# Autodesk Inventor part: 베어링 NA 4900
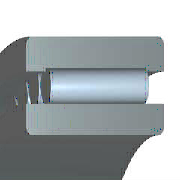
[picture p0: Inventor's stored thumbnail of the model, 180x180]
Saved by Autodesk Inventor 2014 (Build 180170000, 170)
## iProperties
Created: 2009-02
Part Number: 베어링 NA 4900
Material: 스테인리스강
Description: 니들 롤러 베어링 - 경계 치수 및 공차
Document SubType Name: Modeling
Standard: KS B 2029
Designer: SeoGD™
Standards Organization: KS
Language: ko-KR
Size Designation: NA 4900 - 10 x 22 x 13
Categories: <MemberInstance><Categories><Category DisplayName="샤프트 부품" InternalName="7f7aeb1f-a693-4053-b835-cee3144e0d98" Mnemonic="SHFT"><Category DisplayName="베어링" Inter
Density: 8.08 g/cm^3
Appearance: 반광택
Mass: 24.488 g
Surface Area: 38.613 cm^2
Volume: 3.0307 cm^3
IsCustomPart: 0
Author: SeoGD™
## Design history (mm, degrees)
sketch "스케치"
  geometry: L1 (1.857, 9)-(11.143, 9); L2 (11.143, 9)-(11.143, 7); L3 (13, 7)-(0, 7); L4 (1.857, 7)-(1.857, 9); L5 (1.857, 8)-(11.143, 8); L6 (6.5, 8)-(6.5, 7); L7 (0, 5)-(13, 5); L8 (0, 11)-(13, 11); L9 (13, 5)-(13, 7); L10 (13, 8.8)-(13, 11); L11 (1.857, 8.8)-(0, 8.8); L12 (11.143, 8.8)-(13, 8.8); L13 (-6, 0)-(36, 0) reference; L14 (0, -1.9)-(0, 14.9) reference
  constraints: 24 end point, 8 point on line, 3 midpoint, 3 parallel, 3 perpendicular, 2 symmetric about line, 1 horizontal, 1 other
  dimensions: "d6" = 10 diameter of L7 L13 (= WD); "d7" = 14 diameter of L3 L13 (= KID1); "d8" = 22 diameter of L8 L13 (= BD); "d9" = 16 diameter of L6.start L13 (= 0.5 x WD + 0.5 x BD); "d10" = 17.6 diameter of L12 L13 (= 0.9 x BD + 0.9 x WD - 0.8 x KID1); "d11" = 18 diameter of L1 L13 (= BD + WD - KID1); "d12" = 1.85714 distance between parallel lines of L14 L4 (= 0.142857 x KB); "d13" = 13 distance between parallel lines of L14 L9 (= KB); "d14" = 11.14286 distance between parallel lines of L14 L2 (= 0.857143 x KB)
revolve "본체" stored, may be unused: angle "d17" = 90 deg
revolve "롤러" stored, may be unused: angle "d18" = 90 deg
pattern_circular "IDS_ARRAYROLLER[SIMPL:T]" dims angle "d2" = 360 deg
body "Solid1"
fillet "모깎기1" dims "d0" = 0.3 (= KRS)
other parameters: "WD" = 10 [user parameter; used in 6 equation terms], "BD" = 22 [user parameter; used in 6 equation terms], "KB" = 13 [user parameter; used in 3 equation terms], "KID1" = 14 [user parameter; used in 4 equation terms], "KRS" = 0.3 [user parameter; used in 1 equation term], "d3" = 0, "d4" = 0, "d5" = 0, "d15" = 0, "d16" = 0, "BC0" = 9150000 [user parameter], "WR" = 5 (= 0.5 x WD) [user parameter], "BBA" = 0 [user parameter], "BC" = 8150000 [user parameter], "BR" = 11 (= 0.5 x BD) [user parameter]
